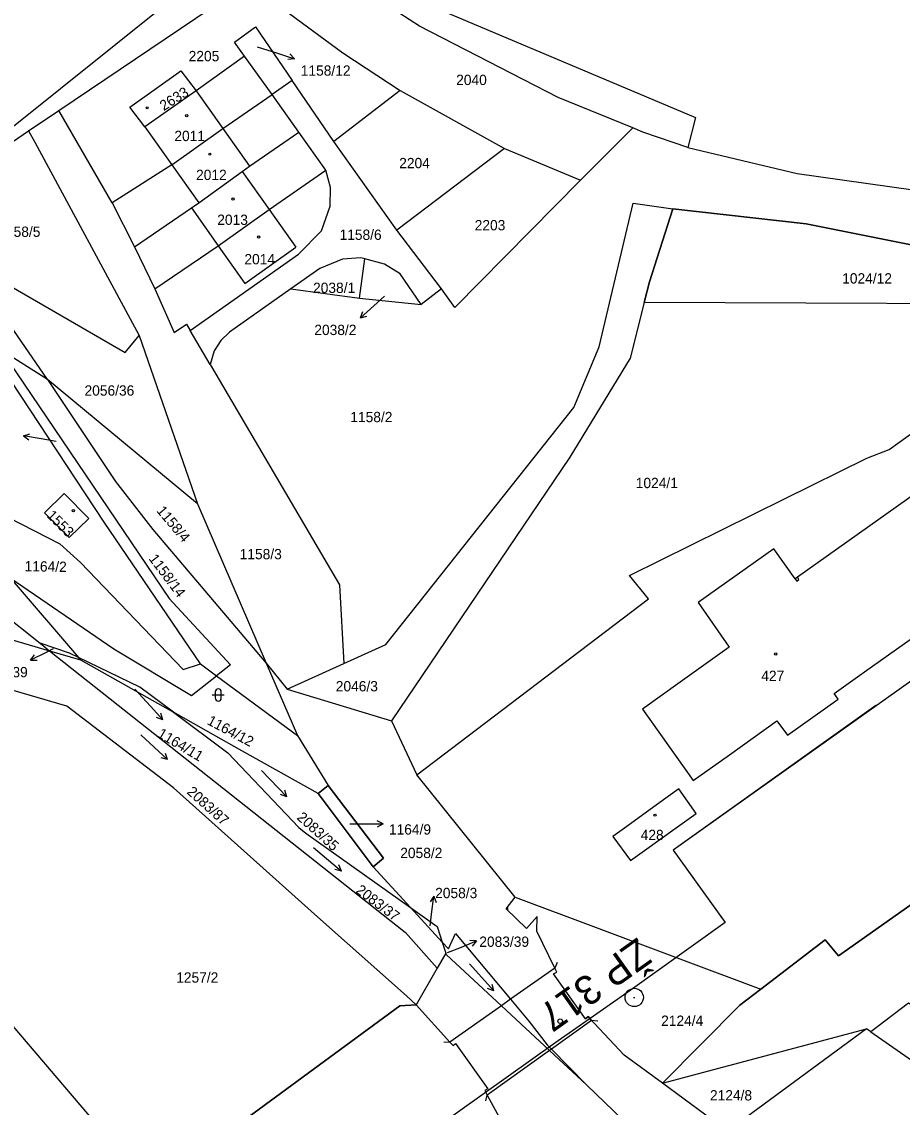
# Model space of a CAD drawing. Extents: x -793666 to -785424, y -1118958 to -1108761.
# Drawn here: x -792489.4 to -792344.1, y -1109962 to -1109782.8 of the extents above; entities that cross this region are included whole.
import ezdxf

# ---------------------------------------------------------------- set-up
doc = ezdxf.new("R2010")
doc.units = 0
for name, color, linetype in [('1', 7, 'Continuous'), ('1_2000 - úřady', 7, 'Continuous'), ('Hranice parcel', 7, 'Continuous'), ('Parcelní čísla', 7, 'Continuous'), ('Pop  PČ popisy', 7, 'Continuous'), ('Vnitřní kresba', 7, 'Continuous'), ('Vrstva 44', 7, 'Continuous'), ('Vrstva 53', 7, 'Continuous'), ('Vrstva 63', 7, 'Continuous'), ('Značky budov', 7, 'Continuous'), ('Značky kultur', 7, 'Continuous')]:
    doc.layers.add(name, color=color, linetype=linetype)

msp = doc.modelspace()

# ---------------------------------------------------------------- linework, layer by layer
at = {"layer": '1'}
for p, q in [((-792348.43, -1109895.7), (-792381.88, -1109919.59)), ((-792381.88, -1109919.59), (-792373.33, -1109931.54)), ((-792373.33, -1109931.54), (-792389.4, -1109943.05)), ((-792389.4, -1109943.05), (-792401.43, -1109951.47)), ((-792396.36, -1109947.46), (-792395.96, -1109947.08)), ((-792395.96, -1109947.08), (-792395.36, -1109947.72)), ((-792401.43, -1109951.47), (-792421.14, -1109965.5)), ((-792402.3, -1109952.67), (-792412.59, -1109960.02)), ((-792412.51, -1109959), (-792413, -1109959.27)), ((-792413, -1109959.27), (-792412.59, -1109960.02))]:
    msp.add_line(p, q, dxfattribs=at)
msp.add_lwpolyline([(-792262.89, -1109847.12), (-792303.98, -1109875.73), (-792309.37, -1109867.98), (-792381.88, -1109919.59), (-792373.33, -1109931.54)], dxfattribs=at)
msp.add_circle((-792400.55, -1109947.82), 0.375, dxfattribs=at)
msp.add_circle((-792400.55, -1109947.82), 0.375, dxfattribs=at)
at = {"layer": '1_2000 - úřady'}
msp.add_lwpolyline([(-791938.08, -1109742.36), (-792598.01, -1110271.46), (-792786.15, -1110036.8), (-792126.22, -1109507.7)], close=True, dxfattribs=at)
at = {"layer": 'Hranice parcel'}
for p, q in [((-792483.31, -1109797.44), (-792452.06, -1109776.34)), ((-792452.63, -1109788.46), (-792460.65, -1109794.16)), ((-792448.1, -1109794.81), (-792452.63, -1109788.46)), ((-792444.79, -1109792.49), (-792448.1, -1109794.81)), ((-792437.9, -1109802.53), (-792444.79, -1109792.49)), ((-792460.65, -1109794.16), (-792469.09, -1109800.15)), ((-792443.67, -1109801.02), (-792448.1, -1109794.81)), ((-792426.99, -1109794.1), (-792437.9, -1109802.53)), ((-792426.99, -1109794.1), (-792409.73, -1109803.7)), ((-792488.29, -1109800.79), (-792483.31, -1109797.44)), ((-792474.47, -1109812.69), (-792483.31, -1109797.44)), ((-792469.09, -1109800.15), (-792464.64, -1109806.41)), ((-792397.2, -1109808.96), (-792388.57, -1109800.3)), ((-792510.02, -1109815.62), (-792488.29, -1109800.79)), ((-792439.22, -1109807.28), (-792443.67, -1109801.02)), ((-792427.53, -1109817.2), (-792437.9, -1109802.53)), ((-792409.73, -1109803.7), (-792427.53, -1109817.2)), ((-792409.73, -1109803.7), (-792397.2, -1109808.96)), ((-792464.64, -1109806.41), (-792474.47, -1109812.69)), ((-792474.47, -1109812.69), (-792470.81, -1109819.97)), ((-792420.12, -1109826.88), (-792427.53, -1109817.2)), ((-792470.81, -1109819.97), (-792467.43, -1109826.89)), ((-792433.7, -1109828.4), (-792432.81, -1109821.94)), ((-792444.99, -1109826.89), (-792433.7, -1109828.4)), ((-792420.12, -1109826.88), (-792423.51, -1109829.46)), ((-792433.7, -1109828.4), (-792423.51, -1109829.46)), ((-792470.06, -1109834.57), (-792460.44, -1109862.36)), ((-792458.34, -1109839.35), (-792461.61, -1109833.78)), ((-792485.15, -1109841.88), (-792492.83, -1109837.02)), ((-792460.44, -1109862.36), (-792485.15, -1109841.88)), ((-792460.44, -1109862.36), (-792449.06, -1109888.71)), ((-792491.34, -1109874.62), (-792480.06, -1109887.74)), ((-792500.99, -1109881.89), (-792484.82, -1109886.64)), ((-792486.38, -1109885.41), (-792484.82, -1109886.64)), ((-792484.82, -1109886.64), (-792479.72, -1109888.14)), ((-792479.72, -1109888.14), (-792480.06, -1109887.74)), ((-792479.72, -1109888.14), (-792464.39, -1109896.81)), ((-792459.92, -1109888.82), (-792457.26, -1109890.78)), ((-792449.06, -1109888.71), (-792445.59, -1109893)), ((-792449.06, -1109888.71), (-792443.92, -1109900.63)), ((-792445.59, -1109893), (-792436.24, -1109888.75)), ((-792457.26, -1109890.78), (-792443.92, -1109900.63)), ((-792445.59, -1109893), (-792428.41, -1109898.21)), ((-792428.41, -1109898.21), (-792424.2, -1109907.16)), ((-792443.92, -1109900.63), (-792438.83, -1109908.9)), ((-792407.99, -1109927.32), (-792424.2, -1109907.16)), ((-792438.83, -1109908.9), (-792440.51, -1109910.24)), ((-792440.51, -1109910.24), (-792431.42, -1109922.33)), ((-792431.42, -1109922.33), (-792425.28, -1109929.04)), ((-792407.99, -1109927.32), (-792367.46, -1109942.54)), ((-792425.28, -1109929.04), (-792420.03, -1109934.77)), ((-792420.03, -1109934.77), (-792419.43, -1109936.6)), ((-792419.43, -1109936.6), (-792420.84, -1109939.05)), ((-792420.84, -1109939.05), (-792424.33, -1109945.11)), ((-792496.95, -1109941.57), (-792468.07, -1109975.45)), ((-792394.9, -1109948.21), (-792395.36, -1109947.72)), ((-792383.68, -1109958.07), (-792350, -1109949.1)), ((-792350, -1109949.1), (-792372.92, -1109965.97)), ((-792349.29, -1109949.6), (-792350, -1109949.1)), ((-792349.29, -1109949.6), (-792300.79, -1109983.35)), ((-792372.92, -1109965.97), (-792383.68, -1109958.07))]:
    msp.add_line(p, q, dxfattribs=at)
for points in [[(-792453.21, -1109753.19), (-792420.77, -1109780.63), (-792378.22, -1109798.57), (-792379.5, -1109803.55)], [(-792388.57, -1109800.3), (-792400.89, -1109795.29), (-792423.79, -1109783.49), (-792432.31, -1109777.95), (-792440.35, -1109771.76), (-792444.74, -1109768.18)], [(-792452.06, -1109776.34), (-792436.41, -1109787.92), (-792426.99, -1109794.1)], [(-792452.63, -1109788.46), (-792454.28, -1109786.15), (-792450.86, -1109783.63), (-792444.79, -1109792.49)], [(-792469.09, -1109800.15), (-792471.56, -1109796.86), (-792463.15, -1109790.86), (-792460.65, -1109794.16)], [(-792464.64, -1109806.41), (-792456.22, -1109800.39), (-792448.1, -1109794.81)], [(-792379.5, -1109803.55), (-792386.9, -1109800.98), (-792388.57, -1109800.3)], [(-792488.29, -1109800.79), (-792487.25, -1109802.64), (-792470.06, -1109834.57)], [(-792470.81, -1109819.97), (-792461.42, -1109813.53), (-792460.19, -1109812.66), (-792453.04, -1109807.51), (-792451.82, -1109806.62), (-792443.67, -1109801.02)], [(-792379.5, -1109803.55), (-792361.45, -1109807.85), (-792342.29, -1109810.51), (-792323.04, -1109810.54), (-792302.75, -1109808.06), (-792283.96, -1109804.89)], [(-792467.43, -1109826.89), (-792457.01, -1109819.76), (-792448.61, -1109813.76), (-792439.22, -1109807.28)], [(-792461.61, -1109833.78), (-792451.94, -1109826.94), (-792443.73, -1109821.13), (-792439.92, -1109817.32), (-792438.5, -1109813.23), (-792438.45, -1109810.15), (-792439.22, -1109807.28)], [(-792397.2, -1109808.96), (-792417.93, -1109829.97), (-792420.12, -1109826.88)], [(-792436.24, -1109888.75), (-792429.34, -1109885.63), (-792398.28, -1109846.46), (-792394.13, -1109836.46), (-792388.49, -1109812.75), (-792381.95, -1109813.67)], [(-792381.95, -1109813.67), (-792385.8, -1109825.7), (-792386.68, -1109829.15)], [(-792295.56, -1109816.94), (-792301.6, -1109817.55), (-792322.02, -1109819.61), (-792342.61, -1109819.6), (-792359.93, -1109816.17), (-792381.95, -1109813.67)], [(-792485.15, -1109841.88), (-792494.43, -1109828.49), (-792506.9, -1109817.42)], [(-792506.9, -1109817.42), (-792472.33, -1109837.37), (-792470.06, -1109834.57)], [(-792432.81, -1109821.94), (-792433.46, -1109821.77), (-792436.47, -1109822), (-792440.2, -1109823.51), (-792444.99, -1109826.89)], [(-792423.51, -1109829.46), (-792426.95, -1109824.43), (-792429.57, -1109822.83), (-792432.81, -1109821.94)], [(-792467.43, -1109826.89), (-792464.25, -1109834.08), (-792462.25, -1109832.69), (-792461.61, -1109833.78)], [(-792444.99, -1109826.89), (-792455.12, -1109834.05), (-792456.58, -1109835.43), (-792457.64, -1109837.14), (-792458.34, -1109839.35)], [(-792386.68, -1109829.15), (-792389.02, -1109838.35), (-792398.94, -1109854.66), (-792428.41, -1109898.21)], [(-792326.43, -1109839.17), (-792333.34, -1109829.35), (-792386.68, -1109829.15)], [(-792459.92, -1109888.82), (-792475.83, -1109865.41), (-792495.87, -1109835.1)], [(-792492.83, -1109837.02), (-792465.09, -1109878), (-792454.96, -1109888.96), (-792457.26, -1109890.78)], [(-792458.34, -1109839.35), (-792436.95, -1109875.77), (-792436.24, -1109888.75)], [(-792424.2, -1109907.16), (-792385.97, -1109878.06), (-792389.09, -1109874.23), (-792363.55, -1109861.57), (-792349.96, -1109854.83), (-792346.23, -1109853.43), (-792326.43, -1109839.17)], [(-792485.15, -1109841.88), (-792473.92, -1109858.72), (-792467.78, -1109866.63), (-792449.06, -1109888.71)], [(-792350.32, -1109890.12), (-792310.53, -1109861.95), (-792321.58, -1109846.27), (-792361.41, -1109874.49), (-792361.79, -1109874.77), (-792365.28, -1109869.81), (-792377.79, -1109878.69), (-792372.64, -1109886.06), (-792380.76, -1109891.84), (-792386.94, -1109896.32), (-792378.6, -1109908.09), (-792372.63, -1109903.82), (-792364.77, -1109898.2), (-792363.05, -1109900.6), (-792354.69, -1109894.62), (-792355.34, -1109893.72), (-792350.32, -1109890.12)], [(-792506.45, -1109857.05), (-792483.14, -1109869.01), (-792479.72, -1109872.05), (-792462.76, -1109889.76), (-792459.92, -1109888.82)], [(-792478.36, -1109864.79), (-792482.43, -1109860.67), (-792485.69, -1109863.88), (-792481.62, -1109867.94), (-792478.36, -1109864.79)], [(-792491.34, -1109874.62), (-792474.22, -1109886.31), (-792461.4, -1109894.05), (-792457.26, -1109890.78)], [(-792500.99, -1109881.89), (-792498.62, -1109881.31), (-792493.21, -1109880), (-792486.38, -1109885.41)], [(-792367.46, -1109942.54), (-792356.82, -1109934.38), (-792354.59, -1109937.05), (-792274.06, -1109880.18), (-792264.32, -1109887.25)], [(-792424.33, -1109945.11), (-792425.94, -1109943.64), (-792440.58, -1109930.57), (-792464.4, -1109909.3), (-792481.97, -1109895.81), (-792506.88, -1109888.52), (-792518.11, -1109886.06)], [(-792480.06, -1109887.74), (-792481.52, -1109887.04), (-792486.38, -1109885.41)], [(-792484.82, -1109886.64), (-792426.08, -1109933.16), (-792420.84, -1109939.05)], [(-792464.39, -1109896.81), (-792469.93, -1109892.67), (-792480.06, -1109887.74)], [(-792464.39, -1109896.81), (-792455.39, -1109903.53), (-792443.7, -1109915.86), (-792442.51, -1109916.76), (-792425.28, -1109929.04)], [(-792440.51, -1109910.24), (-792453.09, -1109903.18), (-792457.76, -1109900.56), (-792464.39, -1109896.81)], [(-792431.42, -1109922.33), (-792429.71, -1109920.9), (-792438.83, -1109908.9)], [(-792386.62, -1109919.63), (-792381.57, -1109916.02), (-792378.09, -1109913.54), (-792380.99, -1109909.44), (-792384.51, -1109912), (-792389.55, -1109915.67), (-792391.84, -1109917.33), (-792388.96, -1109921.29), (-792386.62, -1109919.63)], [(-792395.36, -1109947.72), (-792395.96, -1109947.08), (-792396.36, -1109947.46), (-792401.63, -1109940.01), (-792401.09, -1109939.74), (-792401.42, -1109939.07), (-792404.43, -1109932.95), (-792404.35, -1109930.54), (-792406.09, -1109932.53), (-792409.46, -1109929.26), (-792407.99, -1109927.32)], [(-792425.28, -1109929.04), (-792420.88, -1109932.17), (-792420.03, -1109934.77)], [(-792325.83, -1109932.23), (-792337.77, -1109941.39), (-792342.64, -1109945.14), (-792343.04, -1109944.85), (-792349.29, -1109949.6)], [(-792420.03, -1109934.77), (-792419.01, -1109935.88), (-792417.84, -1109933.35), (-792408.74, -1109944.21), (-792405.73, -1109947.8), (-792402.71, -1109951.72), (-792401.99, -1109952.45), (-792396.21, -1109958.32)], [(-792396.21, -1109958.32), (-792402.3, -1109952.67), (-792410.26, -1109945.28), (-792419.34, -1109936.86), (-792419.43, -1109936.6)], [(-792383.68, -1109958.07), (-792370.89, -1109945.17), (-792367.46, -1109942.54)], [(-792424.33, -1109945.11), (-792427.01, -1109945.27), (-792468.07, -1109975.45)], [(-792424.33, -1109945.11), (-792418.77, -1109951.27), (-792418.22, -1109951.87), (-792417.83, -1109951.51), (-792412.51, -1109959), (-792413, -1109959.27), (-792412.59, -1109960.02), (-792408.62, -1109967.32)], [(-792383.68, -1109958.07), (-792389.98, -1109953.44), (-792394.9, -1109948.21)], [(-792396.21, -1109958.32), (-792390.22, -1109964.13), (-792343.17, -1110003.9), (-792342.46, -1110004.5), (-792325.49, -1110016.94)]]:
    msp.add_lwpolyline(points, dxfattribs=at)
at = {"layer": 'Pop  PČ popisy'}
for p, q in [((-792450.55, -1109786.89), (-792447.23, -1109787.94)), ((-792447.23, -1109787.94), (-792444.38, -1109788.87)), ((-792444.38, -1109788.87), (-792445.17, -1109788.08)), ((-792444.38, -1109788.87), (-792445.48, -1109789.03)), ((-792429.57, -1109828.1), (-792431.3, -1109829.67)), ((-792431.3, -1109829.67), (-792433.53, -1109831.68)), ((-792433.53, -1109831.68), (-792433.12, -1109830.64)), ((-792433.53, -1109831.68), (-792432.45, -1109831.38)), ((-792489.15, -1109851.15), (-792488.07, -1109850.83)), ((-792486.19, -1109851.67), (-792489.15, -1109851.15)), ((-792489.15, -1109851.15), (-792488.25, -1109851.82)), ((-792483.75, -1109852.09), (-792486.19, -1109851.67)), ((-792484.22, -1109886.36), (-792485.28, -1109886.88)), ((-792485.28, -1109886.88), (-792487.98, -1109888.2)), ((-792487.98, -1109888.2), (-792487.3, -1109887.31)), ((-792487.98, -1109888.2), (-792486.86, -1109888.21)), ((-792470.75, -1109892.97), (-792468.16, -1109895.83)), ((-792468.16, -1109895.83), (-792466.15, -1109898.06)), ((-792466.15, -1109898.06), (-792466.45, -1109896.98)), ((-792466.15, -1109898.06), (-792467.19, -1109897.65)), ((-792435.28, -1109915.25), (-792432.77, -1109915.26)), ((-792432.77, -1109915.26), (-792429.77, -1109915.26)), ((-792429.77, -1109915.26), (-792430.77, -1109914.76)), ((-792429.77, -1109915.26), (-792430.77, -1109915.76)), ((-792421.4, -1109927.19), (-792422.02, -1109928.12)), ((-792421.77, -1109930.17), (-792421.4, -1109927.19)), ((-792421.4, -1109927.19), (-792421.03, -1109928.25)), ((-792422.01, -1109932.1), (-792421.77, -1109930.17)), ((-792417.14, -1109935.7), (-792414.36, -1109934.58)), ((-792414.36, -1109934.58), (-792415.47, -1109934.49)), ((-792414.36, -1109934.58), (-792415.1, -1109935.42)), ((-792419.16, -1109936.5), (-792417.14, -1109935.7))]:
    msp.add_line(p, q, dxfattribs=at)
at = {"layer": 'Vnitřní kresba'}
for p, q in [((-792460.65, -1109794.16), (-792456.22, -1109800.39)), ((-792456.22, -1109800.39), (-792451.82, -1109806.62)), ((-792464.64, -1109806.41), (-792460.19, -1109812.66)), ((-792453.04, -1109807.51), (-792448.61, -1109813.76)), ((-792461.42, -1109813.53), (-792457.01, -1109819.76)), ((-792448.61, -1109813.76), (-792444.16, -1109819.99)), ((-792457.01, -1109819.76), (-792452.62, -1109825.98)), ((-792452.62, -1109825.98), (-792444.16, -1109819.99)), ((-792361.79, -1109874.77), (-792361.51, -1109875.17)), ((-792361.51, -1109875.17), (-792361.14, -1109874.88)), ((-792361.14, -1109874.88), (-792361.41, -1109874.49)), ((-792401.06, -1109938.14), (-792401.42, -1109939.07)), ((-792401.42, -1109939.07), (-792408.74, -1109944.21)), ((-792410.26, -1109945.28), (-792418.77, -1109951.27)), ((-792408.74, -1109944.21), (-792410.26, -1109945.28)), ((-792395.36, -1109947.72), (-792401.99, -1109952.45)), ((-792394.36, -1109947.82), (-792395.36, -1109947.72)), ((-792419.77, -1109951.22), (-792418.77, -1109951.27)), ((-792402.3, -1109952.67), (-792412.59, -1109960.02)), ((-792401.99, -1109952.45), (-792402.3, -1109952.67)), ((-792412.85, -1109960.99), (-792412.59, -1109960.02))]:
    msp.add_line(p, q, dxfattribs=at)
at = {"layer": 'Vrstva 44'}
msp.add_line((-792409.2, -1109929.51), (-792409.2, -1109928.92), dxfattribs=at)
at = {"layer": 'Vrstva 53'}
for points in [[(-792333.34, -1109829.35), (-792386.68, -1109829.15), (-792385.8, -1109825.7), (-792381.95, -1109813.67), (-792359.93, -1109816.17), (-792342.61, -1109819.6)], [(-792363.55, -1109861.57), (-792349.96, -1109854.83), (-792346.23, -1109853.43), (-792326.43, -1109839.17)], [(-792274.06, -1109880.18), (-792354.59, -1109937.05), (-792356.82, -1109934.38), (-792367.46, -1109942.54), (-792370.89, -1109945.17), (-792383.68, -1109958.07), (-792389.98, -1109953.44), (-792394.9, -1109948.21), (-792395.36, -1109947.72), (-792395.96, -1109947.08), (-792396.36, -1109947.46), (-792401.63, -1109940.01), (-792401.09, -1109939.74), (-792401.42, -1109939.07), (-792404.43, -1109932.95), (-792404.35, -1109930.54), (-792406.09, -1109932.53), (-792409.46, -1109929.26), (-792407.99, -1109927.32), (-792424.2, -1109907.16), (-792385.97, -1109878.06), (-792389.09, -1109874.23), (-792363.55, -1109861.57)], [(-792468.07, -1109975.45), (-792427.01, -1109945.27), (-792424.33, -1109945.11), (-792418.77, -1109951.27), (-792418.22, -1109951.87), (-792417.83, -1109951.51), (-792412.51, -1109959), (-792413, -1109959.27), (-792412.59, -1109960.02), (-792408.62, -1109967.32)]]:
    msp.add_lwpolyline(points, dxfattribs=at)
msp.add_lwpolyline([(-792440.51, -1109910.24), (-792438.83, -1109908.9), (-792429.71, -1109920.9), (-792431.42, -1109922.33)], close=True, dxfattribs=at)
at = {"layer": 'Vrstva 63'}
msp.add_line((-792388.43, -1109943.91), (-792388.23, -1109943.91), dxfattribs=at)
msp.add_circle((-792388.33, -1109943.91), 1.51, dxfattribs=at)
at = {"layer": 'Značky budov'}
for centre in [(-792468.71, -1109796.99), (-792462.2, -1109798.29), (-792458.38, -1109804.64), (-792454.55, -1109812.05), (-792450.32, -1109818.32), (-792480.9, -1109863.52), (-792364.98, -1109887.18), (-792384.9, -1109913.8)]:
    msp.add_circle(centre, 0.175, dxfattribs=at)
at = {"layer": 'Značky kultur'}
for p, q in [((-792457.49, -1109893.45), (-792457.49, -1109894.45)), ((-792456.49, -1109894.45), (-792456.49, -1109893.45)), ((-792457.99, -1109893.95), (-792455.99, -1109893.95)), ((-792469.74, -1109900.54), (-792465.35, -1109904.63)), ((-792465.35, -1109904.63), (-792466.41, -1109904.33)), ((-792465.35, -1109904.63), (-792465.72, -1109903.6)), ((-792449.84, -1109906.43), (-792445.67, -1109910.75)), ((-792445.67, -1109910.75), (-792445.99, -1109909.7)), ((-792445.67, -1109910.75), (-792446.71, -1109910.39)), ((-792441.26, -1109919.17), (-792436.66, -1109923.03)), ((-792436.66, -1109923.03), (-792437.09, -1109922.01)), ((-792436.66, -1109923.03), (-792437.73, -1109922.78)), ((-792415.53, -1109938.35), (-792411.52, -1109942.81)), ((-792411.52, -1109942.81), (-792411.8, -1109941.75)), ((-792411.52, -1109942.81), (-792412.54, -1109942.42))]:
    msp.add_line(p, q, dxfattribs=at)
for centre, start, end in [((-792456.99, -1109893.45), 0, 180), ((-792456.99, -1109894.45), 180, 359.9879)]:
    msp.add_arc(centre, 0.5, start, end, dxfattribs=at)

# ---------------------------------------------------------------- texts
at = {"layer": 'Parcelní čísla'}
for s, p in [('2205', (-792461.87, -1109789.29)), ('1158/12', (-792443.37, -1109791.68)), ('2040', (-792417.72, -1109793.22)), ('2011', (-792464.23, -1109802.48)), ('2204', (-792427.12, -1109806.96)), ('2012', (-792460.65, -1109808.91)), ('2013', (-792457.15, -1109816.32)), ('1158/5', (-792493.29, -1109818.3)), ('2203', (-792414.66, -1109817.22)), ('1158/6', (-792436.97, -1109818.8)), ('2014', (-792452.67, -1109822.83)), ('1024/12', (-792354.01, -1109826)), ('2038/1', (-792441.34, -1109827.56)), ('2038/2', (-792441.13, -1109834.51)), ('2056/36', (-792479.06, -1109844.52)), ('1158/2', (-792435.19, -1109848.9)), ('1024/1', (-792388.08, -1109859.79)), ('1158/3', (-792453.45, -1109871.54)), ('1193/39', (-792496.65, -1109891.03)), ('427', (-792367.36, -1109891.64)), ('2046/3', (-792437.59, -1109893.36)), ('1164/9', (-792428.82, -1109917.01)), ('428', (-792387.26, -1109917.92)), ('2058/2', (-792426.95, -1109920.89)), ('2058/3', (-792421.19, -1109927.51)), ('2083/39', (-792413.9, -1109935.55)), ('1257/2', (-792463.93, -1109941.46)), ('2124/4', (-792383.89, -1109948.6)), ('2124/8', (-792375.83, -1109960.92))]:
    msp.add_text(s, height=1.7, dxfattribs=at).set_placement(p)
for s, rotation, p in [('2633', 32, (-792465.98, -1109797.54)), ('1158/4', 310, (-792467.27, -1109863.58)), ('1553', 315, (-792485.42, -1109864.44)), ('1164/2', 359, (-792488.96, -1109873.52)), ('1158/14', 307, (-792468.55, -1109871.46)), ('1164/12', 332, (-792458.97, -1109898.71)), ('1164/11', 329, (-792467.16, -1109900.77)), ('2083/87', 318, (-792462.29, -1109910.13)), ('2083/35', 318, (-792444.14, -1109914.35)), ('2083/37', 323, (-792434.43, -1109926.48))]:
    msp.add_text(s, height=1.7, rotation=rotation, dxfattribs=at).set_placement(p)
at = {"layer": 'Vrstva 63'}
msp.add_text('ŽP 317', height=4.8, rotation=215.4533, dxfattribs=at).set_placement((-792387.76, -1109933.88))

doc.saveas('drawing.dxf')
